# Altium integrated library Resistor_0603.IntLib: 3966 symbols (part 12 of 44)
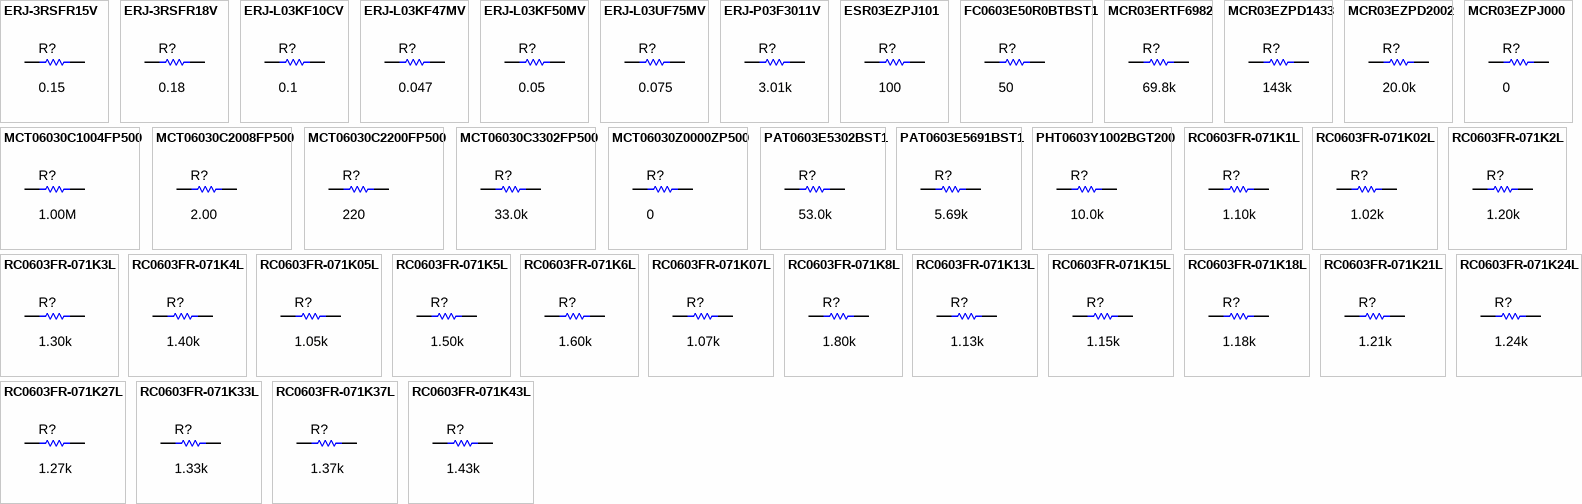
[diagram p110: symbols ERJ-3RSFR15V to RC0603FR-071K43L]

## RC0603FR-071K5L
designator R?  ValueDisplayed: 1.50k  (hidden comment: RC0603FR-071K5L)
RES, 1.50 k, 1%, 0.1 W, 0603; Manufacturer: Yageo America; CompType: Resistor; Value: 1.50k; Res_ohm: 1500; Value_Code: 1k50; Tolerance_%: 1; Power_W: 0.1; Value2: 0.1W; VDC_V: 150; TempCo: 200 ppm/C; SizeArea_mm2: 1.28; SizeX_mm: 1.6; SizeY_mm: 0.8; EIA_Code: E96; U/M: EA; AEC Category: Q200; Green_Lifecycle: Active; Green_REACh: Passed
signal-integrity model Resistor
simulation model Resistor
footprint 0603
footprint 0603M
footprint 0603L
footprint 0603_HV
footprint 0603S
pins: 1, 2

## RC0603FR-071K6L
designator R?  ValueDisplayed: 1.60k  (hidden comment: RC0603FR-071K6L)
RES, 1.60 k, 1%, 0.1 W, 0603; Manufacturer: Yageo America; CompType: Resistor; Value: 1.60k; Res_ohm: 1600; Value_Code: 1k60; Tolerance_%: 1; Power_W: 0.1; Value2: 0.1W; VDC_V: 150; TempCo: 200 ppm/C; SizeArea_mm2: 1.28; SizeX_mm: 1.6; SizeY_mm: 0.8; U/M: EA; AEC Category: Q200
signal-integrity model Resistor
simulation model Resistor
footprint 0603
footprint 0603M
footprint 0603L
footprint 0603_HV
footprint 0603S
pins: 1, 2

## RC0603FR-071K07L
designator R?  ValueDisplayed: 1.07k  (hidden comment: RC0603FR-071K07L)
RES, 1.07 k, 1%, 0.1 W, 0603; Manufacturer: Yageo America; CompType: Resistor; Value: 1.07k; Res_ohm: 1070; Value_Code: 1k07; Tolerance_%: 1; Power_W: 0.1; Value2: 0.1W; VDC_V: 150; TempCo: 200 ppm/C; SizeArea_mm2: 1.28; SizeX_mm: 1.6; SizeY_mm: 0.8; EIA_Code: E96; U/M: EA; AEC Category: Q200
signal-integrity model Resistor
simulation model Resistor
footprint 0603
footprint 0603M
footprint 0603L
footprint 0603_HV
footprint 0603S
pins: 1, 2

## RC0603FR-071K8L
designator R?  ValueDisplayed: 1.80k  (hidden comment: RC0603FR-071K8L)
RES, 1.80 k, 1%, 0.1 W, 0603; Manufacturer: Yageo America; CompType: Resistor; Value: 1.80k; Res_ohm: 1800; Value_Code: 1k80; Tolerance_%: 1; Power_W: 0.1; Value2: 0.1W; VDC_V: 150; TempCo: 200 ppm/C; SizeArea_mm2: 1.28; SizeX_mm: 1.6; SizeY_mm: 0.8; U/M: EA; AEC Category: Q200; Green_Lifecycle: Active; Green_REACh: Passed
signal-integrity model Resistor
simulation model Resistor
footprint 0603
footprint 0603M
footprint 0603L
footprint 0603_HV
footprint 0603S
pins: 1, 2

## RC0603FR-071K13L
designator R?  ValueDisplayed: 1.13k  (hidden comment: RC0603FR-071K13L)
RES, 1.13 k, 1%, 0.1 W, 0603; Manufacturer: Yageo America; CompType: Resistor; Value: 1.13k; Res_ohm: 1130; Value_Code: 1k13; Tolerance_%: 1; Power_W: 0.1; Value2: 0.1W; VDC_V: 150; TempCo: 200 ppm/C; SizeArea_mm2: 1.28; SizeX_mm: 1.6; SizeY_mm: 0.8; EIA_Code: E96; U/M: EA; AEC Category: Q200
signal-integrity model Resistor
simulation model Resistor
footprint 0603
footprint 0603M
footprint 0603L
footprint 0603_HV
footprint 0603S
pins: 1, 2

## RC0603FR-071K15L
designator R?  ValueDisplayed: 1.15k  (hidden comment: RC0603FR-071K15L)
RES, 1.15 k, 1%, 0.1 W, 0603; Manufacturer: Yageo America; CompType: Resistor; Value: 1.15k; Res_ohm: 1150; Value_Code: 1k15; Tolerance_%: 1; Power_W: 0.1; Value2: 0.1W; VDC_V: 150; TempCo: 200 ppm/C; SizeArea_mm2: 1.28; SizeX_mm: 1.6; SizeY_mm: 0.8; EIA_Code: E96; U/M: EA; AEC Category: Q200
signal-integrity model Resistor
simulation model Resistor
footprint 0603
footprint 0603M
footprint 0603L
footprint 0603_HV
footprint 0603S
pins: 1, 2

## RC0603FR-071K18L
designator R?  ValueDisplayed: 1.18k  (hidden comment: RC0603FR-071K18L)
RES, 1.18 k, 1%, 0.1 W, 0603; Manufacturer: Yageo America; CompType: Resistor; Value: 1.18k; Res_ohm: 1180; Value_Code: 1k18; Tolerance_%: 1; Power_W: 0.1; Value2: 0.1W; VDC_V: 150; TempCo: 200 ppm/C; SizeArea_mm2: 1.28; SizeX_mm: 1.6; SizeY_mm: 0.8; EIA_Code: E96; U/M: EA; AEC Category: Q200
signal-integrity model Resistor
simulation model Resistor
footprint 0603
footprint 0603M
footprint 0603L
footprint 0603_HV
footprint 0603S
pins: 1, 2

## RC0603FR-071K21L
designator R?  ValueDisplayed: 1.21k  (hidden comment: RC0603FR-071K21L)
RES, 1.21 k, 1%, 0.1 W, 0603; Manufacturer: Yageo America; CompType: Resistor; Value: 1.21k; Res_ohm: 1210; Value_Code: 1k21; Tolerance_%: 1; Power_W: 0.1; Value2: 0.1W; VDC_V: 150; TempCo: 200 ppm/C; SizeArea_mm2: 1.28; SizeX_mm: 1.6; SizeY_mm: 0.8; EIA_Code: E96; U/M: EA; AEC Category: Q200; Green_Lifecycle: Active; Green_REACh: Passed
signal-integrity model Resistor
simulation model Resistor
footprint 0603
footprint 0603M
footprint 0603L
footprint 0603_HV
footprint 0603S
pins: 1, 2

## RC0603FR-071K24L
designator R?  ValueDisplayed: 1.24k  (hidden comment: RC0603FR-071K24L)
RES, 1.24 k, 1%, 0.1 W, 0603; Manufacturer: Yageo America; CompType: Resistor; Value: 1.24k; Res_ohm: 1240; Value_Code: 1k24; Tolerance_%: 1; Power_W: 0.1; Value2: 0.1W; VDC_V: 150; TempCo: 200 ppm/C; SizeArea_mm2: 1.28; SizeX_mm: 1.6; SizeY_mm: 0.8; EIA_Code: E96; U/M: EA; AEC Category: Q200; Green_Lifecycle: Active; Green_REACh: Passed
signal-integrity model Resistor
simulation model Resistor
footprint 0603
footprint 0603M
footprint 0603L
footprint 0603_HV
footprint 0603S
pins: 1, 2

## RC0603FR-071K27L
designator R?  ValueDisplayed: 1.27k  (hidden comment: RC0603FR-071K27L)
RES, 1.27 k, 1%, 0.1 W, 0603; Manufacturer: Yageo America; CompType: Resistor; Value: 1.27k; Res_ohm: 1270; Value_Code: 1k27; Tolerance_%: 1; Power_W: 0.1; Value2: 0.1W; VDC_V: 150; TempCo: 200 ppm/C; SizeArea_mm2: 1.28; SizeX_mm: 1.6; SizeY_mm: 0.8; EIA_Code: E96; U/M: EA; AEC Category: Q200
signal-integrity model Resistor
simulation model Resistor
footprint 0603
footprint 0603M
footprint 0603L
footprint 0603_HV
footprint 0603S
pins: 1, 2

## RC0603FR-071K33L
designator R?  ValueDisplayed: 1.33k  (hidden comment: RC0603FR-071K33L)
RES, 1.33 k, 1%, 0.1 W, 0603; Manufacturer: Yageo America; CompType: Resistor; Value: 1.33k; Res_ohm: 1330; Value_Code: 1k33; Tolerance_%: 1; Power_W: 0.1; Value2: 0.1W; VDC_V: 150; TempCo: 200 ppm/C; SizeArea_mm2: 1.28; SizeX_mm: 1.6; SizeY_mm: 0.8; EIA_Code: E96; U/M: EA; AEC Category: Q200
signal-integrity model Resistor
simulation model Resistor
footprint 0603
footprint 0603M
footprint 0603L
footprint 0603_HV
footprint 0603S
pins: 1, 2

## RC0603FR-071K37L
designator R?  ValueDisplayed: 1.37k  (hidden comment: RC0603FR-071K37L)
RES, 1.37 k, 1%, 0.1 W, 0603; Manufacturer: Yageo America; CompType: Resistor; Value: 1.37k; Res_ohm: 1370; Value_Code: 1k37; Tolerance_%: 1; Power_W: 0.1; Value2: 0.1W; VDC_V: 150; TempCo: 200 ppm/C; SizeArea_mm2: 1.28; SizeX_mm: 1.6; SizeY_mm: 0.8; EIA_Code: E96; U/M: EA; AEC Category: Q200
signal-integrity model Resistor
simulation model Resistor
footprint 0603
footprint 0603M
footprint 0603L
footprint 0603_HV
footprint 0603S
pins: 1, 2

## RC0603FR-071K43L
designator R?  ValueDisplayed: 1.43k  (hidden comment: RC0603FR-071K43L)
RES, 1.43 k, 1%, 0.1 W, 0603; Manufacturer: Yageo America; CompType: Resistor; Value: 1.43k; Res_ohm: 1430; Value_Code: 1k43; Tolerance_%: 1; Power_W: 0.1; Value2: 0.1W; VDC_V: 150; TempCo: 200 ppm/C; SizeArea_mm2: 1.28; SizeX_mm: 1.6; SizeY_mm: 0.8; EIA_Code: E96; U/M: EA; AEC Category: Q200
signal-integrity model Resistor
simulation model Resistor
footprint 0603
footprint 0603M
footprint 0603L
footprint 0603_HV
footprint 0603S
pins: 1, 2

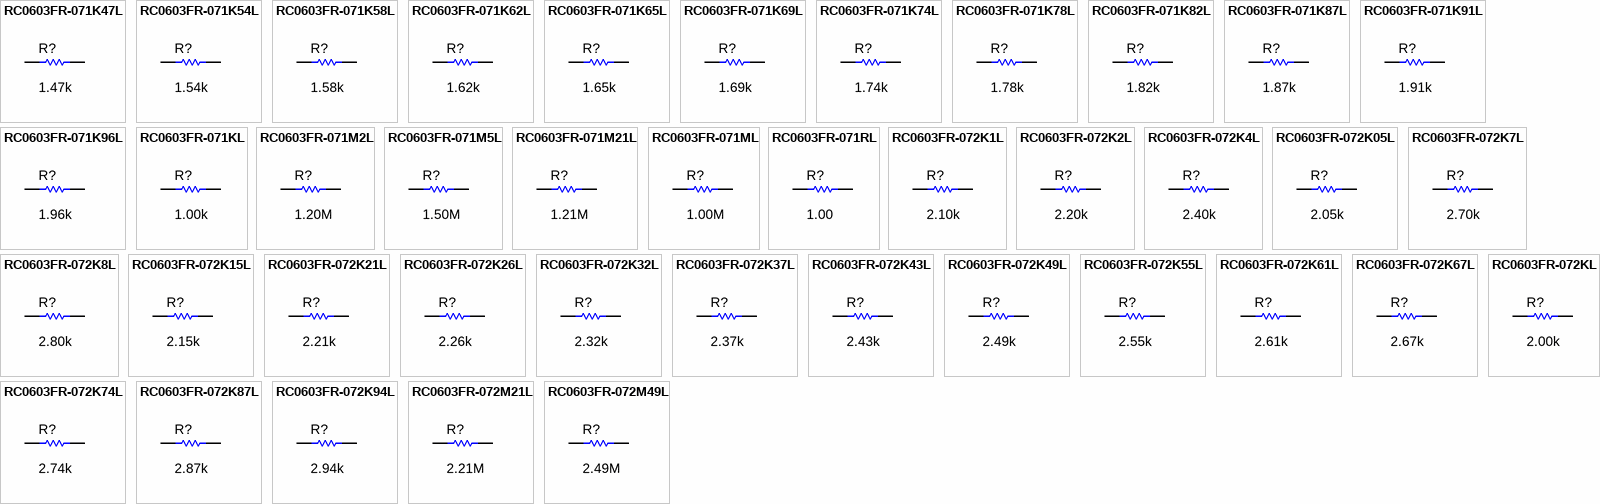
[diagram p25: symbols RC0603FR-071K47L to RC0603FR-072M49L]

## RC0603FR-071K47L
designator R?  ValueDisplayed: 1.47k  (hidden comment: RC0603FR-071K47L)
RES, 1.47 k, 1%, 0.1 W, 0603; Manufacturer: Yageo America; CompType: Resistor; Value: 1.47k; Res_ohm: 1470; Value_Code: 1k47; Tolerance_%: 1; Power_W: 0.1; Value2: 0.1W; VDC_V: 150; TempCo: 200 ppm/C; SizeArea_mm2: 1.28; SizeX_mm: 1.6; SizeY_mm: 0.8; EIA_Code: E96; U/M: EA; AEC Category: Q200
signal-integrity model Resistor
simulation model Resistor
footprint 0603
footprint 0603M
footprint 0603L
footprint 0603_HV
footprint 0603S
pins: 1, 2

## RC0603FR-071K54L
designator R?  ValueDisplayed: 1.54k  (hidden comment: RC0603FR-071K54L)
RES, 1.54 k, 1%, 0.1 W, 0603; Manufacturer: Yageo America; CompType: Resistor; Value: 1.54k; Res_ohm: 1540; Value_Code: 1k54; Tolerance_%: 1; Power_W: 0.1; Value2: 0.1W; VDC_V: 150; TempCo: 200 ppm/C; SizeArea_mm2: 1.28; SizeX_mm: 1.6; SizeY_mm: 0.8; EIA_Code: E96; U/M: EA; AEC Category: Q200; Green_Lifecycle: Not Set; Green_REACh: Incomplete
signal-integrity model Resistor
simulation model Resistor
footprint 0603
footprint 0603M
footprint 0603L
footprint 0603_HV
footprint 0603S
pins: 1, 2

## RC0603FR-071K58L
designator R?  ValueDisplayed: 1.58k  (hidden comment: RC0603FR-071K58L)
RES, 1.58 k, 1%, 0.1 W, 0603; Manufacturer: Yageo America; CompType: Resistor; Value: 1.58k; Res_ohm: 1580; Value_Code: 1k58; Tolerance_%: 1; Power_W: 0.1; Value2: 0.1W; VDC_V: 150; TempCo: 200 ppm/C; SizeArea_mm2: 1.28; SizeX_mm: 1.6; SizeY_mm: 0.8; EIA_Code: E96; U/M: EA; AEC Category: Q200; Green_Lifecycle: Active; Green_REACh: Passed
signal-integrity model Resistor
simulation model Resistor
footprint 0603
footprint 0603M
footprint 0603L
footprint 0603_HV
footprint 0603S
pins: 1, 2

## RC0603FR-071K62L
designator R?  ValueDisplayed: 1.62k  (hidden comment: RC0603FR-071K62L)
RES, 1.62 k, 1%, 0.1 W, 0603; Manufacturer: Yageo America; CompType: Resistor; Value: 1.62k; Res_ohm: 1620; Value_Code: 1k62; Tolerance_%: 1; Power_W: 0.1; Value2: 0.1W; VDC_V: 150; TempCo: 200 ppm/C; SizeArea_mm2: 1.28; SizeX_mm: 1.6; SizeY_mm: 0.8; EIA_Code: E96; U/M: EA; AEC Category: Q200; Green_Lifecycle: Active; Green_REACh: Passed
signal-integrity model Resistor
simulation model Resistor
footprint 0603
footprint 0603M
footprint 0603L
footprint 0603_HV
footprint 0603S
pins: 1, 2

## RC0603FR-071K65L
designator R?  ValueDisplayed: 1.65k  (hidden comment: RC0603FR-071K65L)
RES, 1.65 k, 1%, 0.1 W, 0603; Manufacturer: Yageo America; CompType: Resistor; Value: 1.65k; Res_ohm: 1650; Value_Code: 1k65; Tolerance_%: 1; Power_W: 0.1; Value2: 0.1W; VDC_V: 150; TempCo: 200 ppm/C; SizeArea_mm2: 1.28; SizeX_mm: 1.6; SizeY_mm: 0.8; EIA_Code: E96; U/M: EA; AEC Category: Q200
signal-integrity model Resistor
simulation model Resistor
footprint 0603
footprint 0603M
footprint 0603L
footprint 0603_HV
footprint 0603S
pins: 1, 2

## RC0603FR-071K69L
designator R?  ValueDisplayed: 1.69k  (hidden comment: RC0603FR-071K69L)
RES, 1.69 k, 1%, 0.1 W, 0603; Manufacturer: Yageo America; CompType: Resistor; Value: 1.69k; Res_ohm: 1690; Value_Code: 1k69; Tolerance_%: 1; Power_W: 0.1; Value2: 0.1W; VDC_V: 150; TempCo: 200 ppm/C; SizeArea_mm2: 1.28; SizeX_mm: 1.6; SizeY_mm: 0.8; EIA_Code: E96; U/M: EA; AEC Category: Q200
signal-integrity model Resistor
simulation model Resistor
footprint 0603
footprint 0603M
footprint 0603L
footprint 0603_HV
footprint 0603S
pins: 1, 2

## RC0603FR-071K74L
designator R?  ValueDisplayed: 1.74k  (hidden comment: RC0603FR-071K74L)
RES, 1.74 k, 1%, 0.1 W, 0603; Manufacturer: Yageo America; CompType: Resistor; Value: 1.74k; Res_ohm: 1740; Value_Code: 1k74; Tolerance_%: 1; Power_W: 0.1; Value2: 0.1W; VDC_V: 150; TempCo: 200 ppm/C; SizeArea_mm2: 1.28; SizeX_mm: 1.6; SizeY_mm: 0.8; EIA_Code: E96; U/M: EA; AEC Category: Q200
signal-integrity model Resistor
simulation model Resistor
footprint 0603
footprint 0603M
footprint 0603L
footprint 0603_HV
footprint 0603S
pins: 1, 2

## RC0603FR-071K78L
designator R?  ValueDisplayed: 1.78k  (hidden comment: RC0603FR-071K78L)
RES, 1.78 k, 1%, 0.1 W, 0603; Manufacturer: Yageo America; CompType: Resistor; Value: 1.78k; Res_ohm: 1780; Value_Code: 1k78; Tolerance_%: 1; Power_W: 0.1; Value2: 0.1W; VDC_V: 150; TempCo: 200 ppm/C; SizeArea_mm2: 1.28; SizeX_mm: 1.6; SizeY_mm: 0.8; EIA_Code: E96; U/M: EA; AEC Category: Q200
signal-integrity model Resistor
simulation model Resistor
footprint 0603
footprint 0603M
footprint 0603L
footprint 0603_HV
footprint 0603S
pins: 1, 2

## RC0603FR-071K82L
designator R?  ValueDisplayed: 1.82k  (hidden comment: RC0603FR-071K82L)
RES, 1.82 k, 1%, 0.1 W, 0603; Manufacturer: Yageo America; CompType: Resistor; Value: 1.82k; Res_ohm: 1820; Value_Code: 1k82; Tolerance_%: 1; Power_W: 0.1; Value2: 0.1W; VDC_V: 150; TempCo: 200 ppm/C; SizeArea_mm2: 1.28; SizeX_mm: 1.6; SizeY_mm: 0.8; EIA_Code: E96; U/M: EA; AEC Category: Q200; Green_Lifecycle: Active; Green_REACh: Passed
signal-integrity model Resistor
simulation model Resistor
footprint 0603
footprint 0603M
footprint 0603L
footprint 0603_HV
footprint 0603S
pins: 1, 2

## RC0603FR-071K87L
designator R?  ValueDisplayed: 1.87k  (hidden comment: RC0603FR-071K87L)
RES, 1.87 k, 1%, 0.1 W, 0603; Manufacturer: Yageo America; CompType: Resistor; Value: 1.87k; Res_ohm: 1870; Value_Code: 1k87; Tolerance_%: 1; Power_W: 0.1; Value2: 0.1W; VDC_V: 150; TempCo: 200 ppm/C; SizeArea_mm2: 1.28; SizeX_mm: 1.6; SizeY_mm: 0.8; EIA_Code: E96; U/M: EA; AEC Category: Q200; Green_Lifecycle: Active; Green_REACh: Passed
signal-integrity model Resistor
simulation model Resistor
footprint 0603
footprint 0603M
footprint 0603L
footprint 0603_HV
footprint 0603S
pins: 1, 2

## RC0603FR-071K91L
designator R?  ValueDisplayed: 1.91k  (hidden comment: RC0603FR-071K91L)
RES, 1.91 k, 1%, 0.1 W, 0603; Manufacturer: Yageo America; CompType: Resistor; Value: 1.91k; Res_ohm: 1910; Value_Code: 1k91; Tolerance_%: 1; Power_W: 0.1; Value2: 0.1W; VDC_V: 150; TempCo: 200 ppm/C; SizeArea_mm2: 1.28; SizeX_mm: 1.6; SizeY_mm: 0.8; EIA_Code: E96; U/M: EA; AEC Category: Q200; Green_Lifecycle: Active; Green_REACh: Passed
signal-integrity model Resistor
simulation model Resistor
footprint 0603
footprint 0603M
footprint 0603L
footprint 0603_HV
footprint 0603S
pins: 1, 2

## RC0603FR-071K96L
designator R?  ValueDisplayed: 1.96k  (hidden comment: RC0603FR-071K96L)
RES, 1.96 k, 1%, 0.1 W, 0603; Manufacturer: Yageo America; CompType: Resistor; Value: 1.96k; Res_ohm: 1960; Value_Code: 1k96; Tolerance_%: 1; Power_W: 0.1; Value2: 0.1W; VDC_V: 150; TempCo: 200 ppm/C; SizeArea_mm2: 1.28; SizeX_mm: 1.6; SizeY_mm: 0.8; EIA_Code: E96; U/M: EA; AEC Category: Q200
signal-integrity model Resistor
simulation model Resistor
footprint 0603
footprint 0603M
footprint 0603L
footprint 0603_HV
footprint 0603S
pins: 1, 2

## RC0603FR-071KL
designator R?  ValueDisplayed: 1.00k  (hidden comment: RC0603FR-071KL)
RES, 1.00 k, 1%, 0.1 W, 0603; Manufacturer: Yageo America; CompType: Resistor; Value: 1.00k; Res_ohm: 1000; Value_Code: 1k00; Tolerance_%: 1; Power_W: 0.1; Value2: 0.1W; VDC_V: 150; TempCo: 200 ppm/C; SizeArea_mm2: 1.28; SizeX_mm: 1.6; SizeY_mm: 0.8; EIA_Code: E96; U/M: EA; AEC Category: Q200; Green_Lifecycle: Active; Green_REACh: Passed
signal-integrity model Resistor
simulation model Resistor
footprint 0603
footprint 0603M
footprint 0603L
footprint 0603_HV
footprint 0603S
pins: 1, 2

## RC0603FR-071M2L
designator R?  ValueDisplayed: 1.20M  (hidden comment: RC0603FR-071M2L)
RES, 1.20 M, 1%, 0.1 W, 0603; Manufacturer: Yageo America; CompType: Resistor; Value: 1.20Meg; Res_ohm: 1200000; Value_Code: 1M20; Tolerance_%: 1; Power_W: 0.1; Value2: 0.1W; VDC_V: 150; TempCo: 200 ppm/C; SizeArea_mm2: 1.28; SizeX_mm: 1.6; SizeY_mm: 0.8; U/M: EA; AEC Category: Q200; Green_Lifecycle: Active; Green_REACh: Passed
signal-integrity model Resistor
simulation model Resistor
footprint 0603
footprint 0603M
footprint 0603L
footprint 0603_HV
footprint 0603S
pins: 1, 2

## RC0603FR-071M5L
designator R?  ValueDisplayed: 1.50M  (hidden comment: RC0603FR-071M5L)
RES, 1.50 M, 1%, 0.1 W, 0603; Manufacturer: Yageo America; CompType: Resistor; Value: 1.50Meg; Res_ohm: 1500000; Value_Code: 1M50; Tolerance_%: 1; Power_W: 0.1; Value2: 0.1W; VDC_V: 150; TempCo: 200 ppm/C; SizeArea_mm2: 1.28; SizeX_mm: 1.6; SizeY_mm: 0.8; EIA_Code: E96; U/M: EA; AEC Category: Q200
signal-integrity model Resistor
simulation model Resistor
footprint 0603
footprint 0603M
footprint 0603L
footprint 0603_HV
footprint 0603S
pins: 1, 2

## RC0603FR-071M21L
designator R?  ValueDisplayed: 1.21M  (hidden comment: RC0603FR-071M21L)
RES, 1.21 M, 1%, 0.1 W, 0603; Manufacturer: Yageo America; CompType: Resistor; Value: 1.21Meg; Res_ohm: 1210000; Value_Code: 1M21; Tolerance_%: 1; Power_W: 0.1; Value2: 0.1W; VDC_V: 150; TempCo: 200 ppm/C; SizeArea_mm2: 1.28; SizeX_mm: 1.6; SizeY_mm: 0.8; EIA_Code: E96; U/M: EA; AEC Category: Q200; Green_Lifecycle: Active; Green_REACh: Passed
signal-integrity model Resistor
simulation model Resistor
footprint 0603
footprint 0603M
footprint 0603L
footprint 0603_HV
footprint 0603S
pins: 1, 2

## RC0603FR-071ML
designator R?  ValueDisplayed: 1.00M  (hidden comment: RC0603FR-071ML)
RES, 1.00 M, 1%, 0.1 W, 0603; Manufacturer: Yageo America; CompType: Resistor; Value: 1.00Meg; Res_ohm: 1000000; Value_Code: 1M00; Tolerance_%: 1; Power_W: 0.1; Value2: 0.1W; VDC_V: 150; TempCo: 200 ppm/C; SizeArea_mm2: 1.28; SizeX_mm: 1.6; SizeY_mm: 0.8; EIA_Code: E96; U/M: EA; AEC Category: Q200; Green_Lifecycle: Active; Green_REACh: Passed
signal-integrity model Resistor
simulation model Resistor
footprint 0603
footprint 0603M
footprint 0603L
footprint 0603_HV
footprint 0603S
pins: 1, 2

## RC0603FR-071RL
designator R?  ValueDisplayed: 1.00  (hidden comment: RC0603FR-071RL)
RES, 1.00, 1%, 0.1 W, 0603; Manufacturer: Yageo America; CompType: Resistor; Value: 1.00; Res_ohm: 1; Value_Code: 1R00; Power_W: 0.1; Value2: 0.1W; VDC_V: 150; TempCo: 200 ppm/C; SizeArea_mm2: 1.28; SizeX_mm: 1.6; SizeY_mm: 0.8; EIA_Code: E96; U/M: EA; AEC Category: Q200; Green_Lifecycle: Active; Green_REACh: Passed
signal-integrity model Resistor
simulation model Resistor
footprint 0603
footprint 0603M
footprint 0603L
footprint 0603_HV
footprint 0603S
pins: 1, 2

## RC0603FR-072K1L
designator R?  ValueDisplayed: 2.10k  (hidden comment: RC0603FR-072K1L)
RES, 2.10 k, 1%, 0.1 W, 0603; Manufacturer: Yageo America; CompType: Resistor; Value: 2.10k; Res_ohm: 2100; Value_Code: 2k10; Tolerance_%: 1; Power_W: 0.1; Value2: 0.1W; VDC_V: 150; TempCo: 200 ppm/C; SizeArea_mm2: 1.28; SizeX_mm: 1.6; SizeY_mm: 0.8; EIA_Code: E96; U/M: EA; AEC Category: Q200; Green_Lifecycle: Active; Green_REACh: Passed
signal-integrity model Resistor
simulation model Resistor
footprint 0603
footprint 0603M
footprint 0603L
footprint 0603_HV
footprint 0603S
pins: 1, 2

## RC0603FR-072K2L
designator R?  ValueDisplayed: 2.20k  (hidden comment: RC0603FR-072K2L)
RES, 2.20 k, 1%, 0.1 W, 0603; Manufacturer: Yageo America; CompType: Resistor; Value: 2.20k; Res_ohm: 2200; Value_Code: 2k20; Tolerance_%: 1; Power_W: 0.1; Value2: 0.1W; VDC_V: 150; TempCo: 200 ppm/C; SizeArea_mm2: 1.28; SizeX_mm: 1.6; SizeY_mm: 0.8; U/M: EA; AEC Category: Q200; Green_Lifecycle: Active; Green_REACh: Passed
signal-integrity model Resistor
simulation model Resistor
footprint 0603
footprint 0603M
footprint 0603L
footprint 0603_HV
footprint 0603S
pins: 1, 2

## RC0603FR-072K4L
designator R?  ValueDisplayed: 2.40k  (hidden comment: RC0603FR-072K4L)
RES, 2.40 k, 1%, 0.1 W, 0603; Manufacturer: Yageo America; CompType: Resistor; Value: 2.40k; Res_ohm: 2400; Value_Code: 2k40; Tolerance_%: 1; Power_W: 0.1; Value2: 0.1W; VDC_V: 150; TempCo: 200 ppm/C; SizeArea_mm2: 1.28; SizeX_mm: 1.6; SizeY_mm: 0.8; U/M: EA; AEC Category: Q200
signal-integrity model Resistor
simulation model Resistor
footprint 0603
footprint 0603M
footprint 0603L
footprint 0603_HV
footprint 0603S
pins: 1, 2

## RC0603FR-072K05L
designator R?  ValueDisplayed: 2.05k  (hidden comment: RC0603FR-072K05L)
RES, 2.05 k, 1%, 0.1 W, 0603; Manufacturer: Yageo America; CompType: Resistor; Value: 2.05k; Res_ohm: 2050; Value_Code: 2k05; Tolerance_%: 1; Power_W: 0.1; Value2: 0.1W; VDC_V: 150; TempCo: 200 ppm/C; SizeArea_mm2: 1.28; SizeX_mm: 1.6; SizeY_mm: 0.8; EIA_Code: E96; U/M: EA; AEC Category: Q200; Green_Lifecycle: Active; Green_REACh: Passed
signal-integrity model Resistor
simulation model Resistor
footprint 0603
footprint 0603M
footprint 0603L
footprint 0603_HV
footprint 0603S
pins: 1, 2

## RC0603FR-072K7L
designator R?  ValueDisplayed: 2.70k  (hidden comment: RC0603FR-072K7L)
RES, 2.70 k, 1%, 0.1 W, 0603; Manufacturer: Yageo America; CompType: Resistor; Value: 2.70k; Res_ohm: 2700; Value_Code: 2k70; Tolerance_%: 1; Power_W: 0.1; Value2: 0.1W; VDC_V: 150; TempCo: 200 ppm/C; SizeArea_mm2: 1.28; SizeX_mm: 1.6; SizeY_mm: 0.8; U/M: EA; AEC Category: Q200
signal-integrity model Resistor
simulation model Resistor
footprint 0603
footprint 0603M
footprint 0603L
footprint 0603_HV
footprint 0603S
pins: 1, 2

## RC0603FR-072K8L
designator R?  ValueDisplayed: 2.80k  (hidden comment: RC0603FR-072K8L)
RES, 2.80 k, 1%, 0.1 W, 0603; Manufacturer: Yageo America; CompType: Resistor; Value: 2.80k; Res_ohm: 2800; Value_Code: 2k80; Tolerance_%: 1; Power_W: 0.1; Value2: 0.1W; VDC_V: 150; TempCo: 200 ppm/C; SizeArea_mm2: 1.28; SizeX_mm: 1.6; SizeY_mm: 0.8; EIA_Code: E96; U/M: EA; AEC Category: Q200
signal-integrity model Resistor
simulation model Resistor
footprint 0603
footprint 0603M
footprint 0603L
footprint 0603_HV
footprint 0603S
pins: 1, 2

## RC0603FR-072K15L
designator R?  ValueDisplayed: 2.15k  (hidden comment: RC0603FR-072K15L)
RES, 2.15 k, 1%, 0.1 W, 0603; Manufacturer: Yageo America; CompType: Resistor; Value: 2.15k; Res_ohm: 2150; Value_Code: 2k15; Tolerance_%: 1; Power_W: 0.1; Value2: 0.1W; VDC_V: 150; TempCo: 200 ppm/C; SizeArea_mm2: 1.28; SizeX_mm: 1.6; SizeY_mm: 0.8; EIA_Code: E96; U/M: EA; AEC Category: Q200
signal-integrity model Resistor
simulation model Resistor
footprint 0603
footprint 0603M
footprint 0603L
footprint 0603_HV
footprint 0603S
pins: 1, 2

## RC0603FR-072K21L
designator R?  ValueDisplayed: 2.21k  (hidden comment: RC0603FR-072K21L)
RES, 2.21 k, 1%, 0.1 W, 0603; Manufacturer: Yageo America; CompType: Resistor; Value: 2.21k; Res_ohm: 2210; Value_Code: 2k21; Tolerance_%: 1; Power_W: 0.1; Value2: 0.1W; VDC_V: 150; TempCo: 200 ppm/C; SizeArea_mm2: 1.28; SizeX_mm: 1.6; SizeY_mm: 0.8; EIA_Code: E96; U/M: EA; AEC Category: Q200; Green_Lifecycle: Active; Green_REACh: Passed
signal-integrity model Resistor
simulation model Resistor
footprint 0603
footprint 0603M
footprint 0603L
footprint 0603_HV
footprint 0603S
pins: 1, 2

## RC0603FR-072K26L
designator R?  ValueDisplayed: 2.26k  (hidden comment: RC0603FR-072K26L)
RES, 2.26 k, 1%, 0.1 W, 0603; Manufacturer: Yageo America; CompType: Resistor; Value: 2.26k; Res_ohm: 2260; Value_Code: 2k26; Tolerance_%: 1; Power_W: 0.1; Value2: 0.1W; VDC_V: 150; TempCo: 200 ppm/C; SizeArea_mm2: 1.28; SizeX_mm: 1.6; SizeY_mm: 0.8; EIA_Code: E96; U/M: EA; AEC Category: Q200; Green_Lifecycle: Active; Green_REACh: Passed
signal-integrity model Resistor
simulation model Resistor
footprint 0603
footprint 0603M
footprint 0603L
footprint 0603_HV
footprint 0603S
pins: 1, 2

## RC0603FR-072K32L
designator R?  ValueDisplayed: 2.32k  (hidden comment: RC0603FR-072K32L)
RES, 2.32 k, 1%, 0.1 W, 0603; Manufacturer: Yageo America; CompType: Resistor; Value: 2.32k; Res_ohm: 2320; Value_Code: 2k32; Tolerance_%: 1; Power_W: 0.1; Value2: 0.1W; VDC_V: 150; TempCo: 200 ppm/C; SizeArea_mm2: 1.28; SizeX_mm: 1.6; SizeY_mm: 0.8; EIA_Code: E96; U/M: EA; AEC Category: Q200; Green_Lifecycle: Active; Green_REACh: Passed
signal-integrity model Resistor
simulation model Resistor
footprint 0603
footprint 0603M
footprint 0603L
footprint 0603_HV
footprint 0603S
pins: 1, 2

## RC0603FR-072K37L
designator R?  ValueDisplayed: 2.37k  (hidden comment: RC0603FR-072K37L)
RES, 2.37 k, 1%, 0.1 W, 0603; Manufacturer: Yageo America; CompType: Resistor; Value: 2.37k; Res_ohm: 2370; Value_Code: 2k37; Tolerance_%: 1; Power_W: 0.1; Value2: 0.1W; VDC_V: 150; TempCo: 200 ppm/C; SizeArea_mm2: 1.28; SizeX_mm: 1.6; SizeY_mm: 0.8; EIA_Code: E96; U/M: EA; AEC Category: Q200; Green_Lifecycle: Active; Green_REACh: Passed
signal-integrity model Resistor
simulation model Resistor
footprint 0603
footprint 0603M
footprint 0603L
footprint 0603_HV
footprint 0603S
pins: 1, 2

## RC0603FR-072K43L
designator R?  ValueDisplayed: 2.43k  (hidden comment: RC0603FR-072K43L)
RES, 2.43 k, 1%, 0.1 W, 0603; Manufacturer: Yageo America; CompType: Resistor; Value: 2.43k; Res_ohm: 2430; Value_Code: 2k43; Tolerance_%: 1; Power_W: 0.1; Value2: 0.1W; VDC_V: 150; TempCo: 200 ppm/C; SizeArea_mm2: 1.28; SizeX_mm: 1.6; SizeY_mm: 0.8; EIA_Code: E96; U/M: EA; AEC Category: Q200
signal-integrity model Resistor
simulation model Resistor
footprint 0603
footprint 0603M
footprint 0603L
footprint 0603_HV
footprint 0603S
pins: 1, 2

## RC0603FR-072K49L
designator R?  ValueDisplayed: 2.49k  (hidden comment: RC0603FR-072K49L)
RES, 2.49 k, 1%, 0.1 W, 0603; Manufacturer: Yageo America; CompType: Resistor; Value: 2.49k; Res_ohm: 2490; Value_Code: 2k49; Tolerance_%: 1; Power_W: 0.1; Value2: 0.1W; VDC_V: 150; TempCo: 200 ppm/C; SizeArea_mm2: 1.28; SizeX_mm: 1.6; SizeY_mm: 0.8; EIA_Code: E96; U/M: EA; AEC Category: Q200; Green_Lifecycle: Active; Green_REACh: Passed
signal-integrity model Resistor
simulation model Resistor
footprint 0603
footprint 0603M
footprint 0603L
footprint 0603_HV
footprint 0603S
pins: 1, 2

## RC0603FR-072K55L
designator R?  ValueDisplayed: 2.55k  (hidden comment: RC0603FR-072K55L)
RES, 2.55 k, 1%, 0.1 W, 0603; Manufacturer: Yageo America; CompType: Resistor; Value: 2.55k; Res_ohm: 2550; Value_Code: 2k55; Tolerance_%: 1; Power_W: 0.1; Value2: 0.1W; VDC_V: 150; TempCo: 200 ppm/C; SizeArea_mm2: 1.28; SizeX_mm: 1.6; SizeY_mm: 0.8; EIA_Code: E96; U/M: EA; AEC Category: Q200
signal-integrity model Resistor
simulation model Resistor
footprint 0603
footprint 0603M
footprint 0603L
footprint 0603_HV
footprint 0603S
pins: 1, 2

## RC0603FR-072K61L
designator R?  ValueDisplayed: 2.61k  (hidden comment: RC0603FR-072K61L)
RES, 2.61 k, 1%, 0.1 W, 0603; Manufacturer: Yageo America; CompType: Resistor; Value: 2.61k; Res_ohm: 2610; Value_Code: 2k61; Tolerance_%: 1; Power_W: 0.1; Value2: 0.1W; VDC_V: 150; TempCo: 200 ppm/C; SizeArea_mm2: 1.28; SizeX_mm: 1.6; SizeY_mm: 0.8; EIA_Code: E96; U/M: EA; AEC Category: Q200
signal-integrity model Resistor
simulation model Resistor
footprint 0603
footprint 0603M
footprint 0603L
footprint 0603_HV
footprint 0603S
pins: 1, 2

## RC0603FR-072K67L
designator R?  ValueDisplayed: 2.67k  (hidden comment: RC0603FR-072K67L)
RES, 2.67 k, 1%, 0.1 W, 0603; Manufacturer: Yageo America; CompType: Resistor; Value: 2.67k; Res_ohm: 2670; Value_Code: 2k67; Tolerance_%: 1; Power_W: 0.1; Value2: 0.1W; VDC_V: 150; TempCo: 200 ppm/C; SizeArea_mm2: 1.28; SizeX_mm: 1.6; SizeY_mm: 0.8; EIA_Code: E96; U/M: EA; AEC Category: Q200; Green_Lifecycle: Active; Green_REACh: Passed
signal-integrity model Resistor
simulation model Resistor
footprint 0603
footprint 0603M
footprint 0603L
footprint 0603_HV
footprint 0603S
pins: 1, 2

## RC0603FR-072K74L
designator R?  ValueDisplayed: 2.74k  (hidden comment: RC0603FR-072K74L)
RES, 2.74 k, 1%, 0.1 W, 0603; Manufacturer: Yageo America; CompType: Resistor; Value: 2.74k; Res_ohm: 2740; Value_Code: 2k74; Tolerance_%: 1; Power_W: 0.1; Value2: 0.1W; VDC_V: 150; TempCo: 200 ppm/C; SizeArea_mm2: 1.28; SizeX_mm: 1.6; SizeY_mm: 0.8; EIA_Code: E96; U/M: EA; AEC Category: Q200; Green_Lifecycle: Active; Green_REACh: Passed
signal-integrity model Resistor
simulation model Resistor
footprint 0603
footprint 0603M
footprint 0603L
footprint 0603_HV
footprint 0603S
pins: 1, 2

## RC0603FR-072K87L
designator R?  ValueDisplayed: 2.87k  (hidden comment: RC0603FR-072K87L)
RES, 2.87 k, 1%, 0.1 W, 0603; Manufacturer: Yageo America; CompType: Resistor; Value: 2.87k; Res_ohm: 2870; Value_Code: 2k87; Tolerance_%: 1; Power_W: 0.1; Value2: 0.1W; VDC_V: 150; TempCo: 200 ppm/C; SizeArea_mm2: 1.28; SizeX_mm: 1.6; SizeY_mm: 0.8; EIA_Code: E96; U/M: EA; AEC Category: Q200
signal-integrity model Resistor
simulation model Resistor
footprint 0603
footprint 0603M
footprint 0603L
footprint 0603_HV
footprint 0603S
pins: 1, 2

## RC0603FR-072K94L
designator R?  ValueDisplayed: 2.94k  (hidden comment: RC0603FR-072K94L)
RES, 2.94 k, 1%, 0.1 W, 0603; Manufacturer: Yageo America; CompType: Resistor; Value: 2.94k; Res_ohm: 2940; Value_Code: 2k94; Tolerance_%: 1; Power_W: 0.1; Value2: 0.1W; VDC_V: 150; TempCo: 200 ppm/C; SizeArea_mm2: 1.28; SizeX_mm: 1.6; SizeY_mm: 0.8; EIA_Code: E96; U/M: EA; AEC Category: Q200
signal-integrity model Resistor
simulation model Resistor
footprint 0603
footprint 0603M
footprint 0603L
footprint 0603_HV
footprint 0603S
pins: 1, 2

## RC0603FR-072KL
designator R?  ValueDisplayed: 2.00k  (hidden comment: RC0603FR-072KL)
RES, 2.00 k, 1%, 0.1 W, 0603; Manufacturer: Yageo America; CompType: Resistor; Value: 2.00k; Res_ohm: 2000; Value_Code: 2k00; Tolerance_%: 1; Power_W: 0.1; Value2: 0.1W; VDC_V: 150; TempCo: 200 ppm/C; SizeArea_mm2: 1.28; SizeX_mm: 1.6; SizeY_mm: 0.8; EIA_Code: E96; U/M: EA; AEC Category: Q200; Green_Lifecycle: Active; Green_REACh: Passed
signal-integrity model Resistor
simulation model Resistor
footprint 0603
footprint 0603M
footprint 0603L
footprint 0603_HV
footprint 0603S
pins: 1, 2

## RC0603FR-072M21L
designator R?  ValueDisplayed: 2.21M  (hidden comment: RC0603FR-072M21L)
RES, 2.21 M, 1%, 0.1 W, 0603; Manufacturer: Yageo America; CompType: Resistor; Value: 2.21Meg; Res_ohm: 2210000; Value_Code: 2M21; Tolerance_%: 1; Power_W: 0.1; Value2: 0.1W; VDC_V: 150; TempCo: 200 ppm/C; SizeArea_mm2: 1.28; SizeX_mm: 1.6; SizeY_mm: 0.8; EIA_Code: E96; U/M: EA; AEC Category: Q200; Green_Lifecycle: Active; Green_REACh: Passed
signal-integrity model Resistor
simulation model Resistor
footprint 0603
footprint 0603M
footprint 0603L
footprint 0603_HV
footprint 0603S
pins: 1, 2

## RC0603FR-072M49L
designator R?  ValueDisplayed: 2.49M  (hidden comment: RC0603FR-072M49L)
RES, 2.49 M, 1%, 0.1 W, 0603; Manufacturer: Yageo America; CompType: Resistor; Value: 2.49Meg; Res_ohm: 2490000; Value_Code: 2M49; Tolerance_%: 1; Power_W: 0.1; Value2: 0.1W; VDC_V: 150; TempCo: 200 ppm/C; SizeArea_mm2: 1.28; SizeX_mm: 1.6; SizeY_mm: 0.8; EIA_Code: E96; U/M: EA; AEC Category: Q200
signal-integrity model Resistor
simulation model Resistor
footprint 0603
footprint 0603M
footprint 0603L
footprint 0603_HV
footprint 0603S
pins: 1, 2

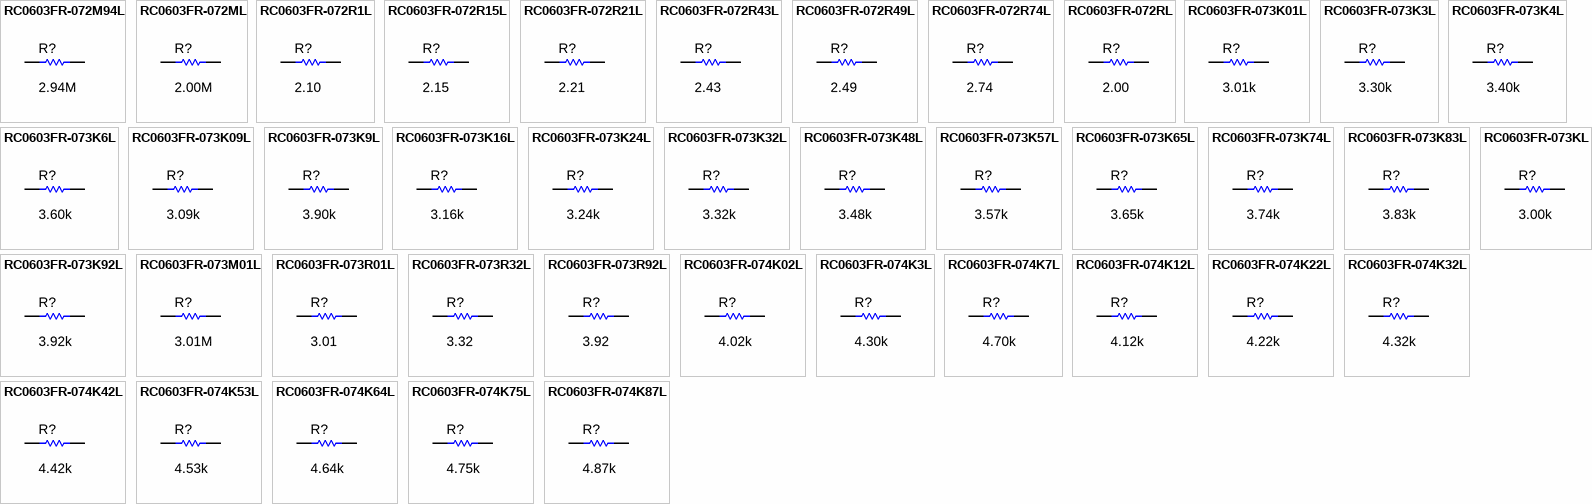
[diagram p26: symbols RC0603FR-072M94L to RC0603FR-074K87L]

## RC0603FR-072M94L
designator R?  ValueDisplayed: 2.94M  (hidden comment: RC0603FR-072M94L)
RES, 2.94 M, 1%, 0.1 W, 0603; Manufacturer: Yageo America; CompType: Resistor; Value: 2.94Meg; Res_ohm: 2940000; Value_Code: 2M94; Tolerance_%: 1; Power_W: 0.1; Value2: 0.1W; VDC_V: 150; TempCo: 200 ppm/C; SizeArea_mm2: 1.28; SizeX_mm: 1.6; SizeY_mm: 0.8; EIA_Code: E96; U/M: EA; AEC Category: Q200
signal-integrity model Resistor
simulation model Resistor
footprint 0603
footprint 0603M
footprint 0603L
footprint 0603_HV
footprint 0603S
pins: 1, 2

## RC0603FR-072ML
designator R?  ValueDisplayed: 2.00M  (hidden comment: RC0603FR-072ML)
RES, 2.00 M, 1%, 0.1 W, 0603; Manufacturer: Yageo America; CompType: Resistor; Value: 2.00Meg; Res_ohm: 2000000; Value_Code: 2M00; Tolerance_%: 1; Power_W: 0.1; Value2: 0.1W; VDC_V: 150; TempCo: 200 ppm/C; SizeArea_mm2: 1.28; SizeX_mm: 1.6; SizeY_mm: 0.8; EIA_Code: E96; U/M: EA; AEC Category: Q200; Green_Lifecycle: Active; Green_REACh: Passed
signal-integrity model Resistor
simulation model Resistor
footprint 0603
footprint 0603M
footprint 0603L
footprint 0603_HV
footprint 0603S
pins: 1, 2

## RC0603FR-072R1L
designator R?  ValueDisplayed: 2.10  (hidden comment: RC0603FR-072R1L)
RES, 2.10, 1%, 0.1 W, 0603; Manufacturer: Yageo America; CompType: Resistor; Value: 2.10; Res_ohm: 2.1; Value_Code: 2R10; Tolerance_%: 1; Power_W: 0.1; Value2: 0.1W; VDC_V: 150; TempCo: 200 ppm/C; SizeArea_mm2: 1.28; SizeX_mm: 1.6; SizeY_mm: 0.8; EIA_Code: E96; U/M: EA; AEC Category: Q200
signal-integrity model Resistor
simulation model Resistor
footprint 0603
footprint 0603M
footprint 0603L
footprint 0603_HV
footprint 0603S
pins: 1, 2

## RC0603FR-072R15L
designator R?  ValueDisplayed: 2.15  (hidden comment: RC0603FR-072R15L)
RES, 2.15, 1%, 0.1 W, 0603; Manufacturer: Yageo America; CompType: Resistor; Value: 2.15; Value_Code: 2R15; Tolerance_%: 1; Power_W: 0.1; Value2: 0.1W; VDC_V: 150; TempCo: 200 ppm/C; SizeArea_mm2: 1.28; SizeX_mm: 1.6; SizeY_mm: 0.8; EIA_Code: E96; U/M: EA; AEC Category: Q200
signal-integrity model Resistor
simulation model Resistor
footprint 0603
footprint 0603M
footprint 0603L
footprint 0603_HV
footprint 0603S
pins: 1, 2

## RC0603FR-072R21L
designator R?  ValueDisplayed: 2.21  (hidden comment: RC0603FR-072R21L)
RES, 2.21, 1%, 0.1 W, 0603; Manufacturer: Yageo America; CompType: Resistor; Value: 2.21; Value_Code: 2R21; Tolerance_%: 1; Power_W: 0.1; Value2: 0.1W; VDC_V: 150; TempCo: 200 ppm/C; SizeArea_mm2: 1.28; SizeX_mm: 1.6; SizeY_mm: 0.8; EIA_Code: E96; U/M: EA; AEC Category: Q200
signal-integrity model Resistor
simulation model Resistor
footprint 0603
footprint 0603M
footprint 0603L
footprint 0603_HV
footprint 0603S
pins: 1, 2

## RC0603FR-072R43L
designator R?  ValueDisplayed: 2.43  (hidden comment: RC0603FR-072R43L)
RES, 2.43, 1%, 0.1 W, 0603; Manufacturer: Yageo America; CompType: Resistor; Value: 2.43; Value_Code: 2R43; Tolerance_%: 1; Power_W: 0.1; Value2: 0.1W; VDC_V: 150; TempCo: 200 ppm/C; SizeArea_mm2: 1.28; SizeX_mm: 1.6; SizeY_mm: 0.8; EIA_Code: E96; U/M: EA; AEC Category: Q200
signal-integrity model Resistor
simulation model Resistor
footprint 0603
footprint 0603M
footprint 0603L
footprint 0603_HV
footprint 0603S
pins: 1, 2

## RC0603FR-072R49L
designator R?  ValueDisplayed: 2.49  (hidden comment: RC0603FR-072R49L)
RES, 2.49, 1%, 0.1 W, 0603; Manufacturer: Yageo America; CompType: Resistor; Value: 2.49; Value_Code: 2R49; Tolerance_%: 1; Power_W: 0.1; Value2: 0.1W; VDC_V: 150; TempCo: 200 ppm/C; SizeArea_mm2: 1.28; SizeX_mm: 1.6; SizeY_mm: 0.8; EIA_Code: E96; U/M: EA; AEC Category: Q200
signal-integrity model Resistor
simulation model Resistor
footprint 0603
footprint 0603M
footprint 0603L
footprint 0603_HV
footprint 0603S
pins: 1, 2

## RC0603FR-072R74L
designator R?  ValueDisplayed: 2.74  (hidden comment: RC0603FR-072R74L)
RES, 2.74, 1%, 0.1 W, 0603; Manufacturer: Yageo America; CompType: Resistor; Value: 2.74; Value_Code: 2R74; Tolerance_%: 1; Power_W: 0.1; Value2: 0.1W; VDC_V: 150; TempCo: 200 ppm/C; SizeArea_mm2: 1.28; SizeX_mm: 1.6; SizeY_mm: 0.8; EIA_Code: E96; U/M: EA; AEC Category: Q200
signal-integrity model Resistor
simulation model Resistor
footprint 0603
footprint 0603M
footprint 0603L
footprint 0603_HV
footprint 0603S
pins: 1, 2

## RC0603FR-072RL
designator R?  ValueDisplayed: 2.00  (hidden comment: RC0603FR-072RL)
RES, 2.00, 1%, 0.1 W, 0603; Manufacturer: Yageo America; CompType: Resistor; Value: 2.00; Res_ohm: 2; Value_Code: 2R00; Tolerance_%: 1; Power_W: 0.1; Value2: 0.1W; VDC_V: 150; TempCo: 200 ppm/C; SizeArea_mm2: 1.28; SizeX_mm: 1.6; SizeY_mm: 0.8; EIA_Code: E96; U/M: EA; AEC Category: Q200
signal-integrity model Resistor
simulation model Resistor
footprint 0603
footprint 0603M
footprint 0603L
footprint 0603_HV
footprint 0603S
pins: 1, 2

## RC0603FR-073K01L
designator R?  ValueDisplayed: 3.01k  (hidden comment: RC0603FR-073K01L)
RES, 3.01 k, 1%, 0.1 W, 0603; Manufacturer: Yageo America; CompType: Resistor; Value: 3.01k; Res_ohm: 3010; Value_Code: 3k01; Tolerance_%: 1; Power_W: 0.1; Value2: 0.1W; VDC_V: 150; TempCo: 200 ppm/C; SizeArea_mm2: 1.28; SizeX_mm: 1.6; SizeY_mm: 0.8; EIA_Code: E96; U/M: EA; AEC Category: Q200; Green_Lifecycle: Active; Green_REACh: Passed
signal-integrity model Resistor
simulation model Resistor
footprint 0603
footprint 0603M
footprint 0603L
footprint 0603_HV
footprint 0603S
pins: 1, 2

## RC0603FR-073K3L
designator R?  ValueDisplayed: 3.30k  (hidden comment: RC0603FR-073K3L)
RES, 3.30 k, 1%, 0.1 W, 0603; Manufacturer: Yageo America; CompType: Resistor; Value: 3.30k; Res_ohm: 3300; Value_Code: 3k30; Tolerance_%: 1; Power_W: 0.1; Value2: 0.1W; VDC_V: 150; TempCo: 200 ppm/C; SizeArea_mm2: 1.28; SizeX_mm: 1.6; SizeY_mm: 0.8; U/M: EA; AEC Category: Q200; Green_Lifecycle: Active; Green_REACh: Passed
signal-integrity model Resistor
simulation model Resistor
footprint 0603
footprint 0603M
footprint 0603L
footprint 0603_HV
footprint 0603S
pins: 1, 2

## RC0603FR-073K4L
designator R?  ValueDisplayed: 3.40k  (hidden comment: RC0603FR-073K4L)
RES, 3.40 k, 1%, 0.1 W, 0603; Manufacturer: Yageo America; CompType: Resistor; Value: 3.40k; Res_ohm: 3400; Value_Code: 3k40; Tolerance_%: 1; Power_W: 0.1; Value2: 0.1W; VDC_V: 150; TempCo: 200 ppm/C; SizeArea_mm2: 1.28; SizeX_mm: 1.6; SizeY_mm: 0.8; EIA_Code: E96; U/M: EA; AEC Category: Q200; Green_Lifecycle: Active; Green_REACh: Passed
signal-integrity model Resistor
simulation model Resistor
footprint 0603
footprint 0603M
footprint 0603L
footprint 0603_HV
footprint 0603S
pins: 1, 2

## RC0603FR-073K6L
designator R?  ValueDisplayed: 3.60k  (hidden comment: RC0603FR-073K6L)
RES, 3.60 k, 1%, 0.1 W, 0603; Manufacturer: Yageo America; CompType: Resistor; Value: 3.60k; Res_ohm: 3600; Value_Code: 3k60; Tolerance_%: 1; Power_W: 0.1; Value2: 0.1W; VDC_V: 150; TempCo: 200 ppm/C; SizeArea_mm2: 1.28; SizeX_mm: 1.6; SizeY_mm: 0.8; U/M: EA; AEC Category: Q200; Green_Lifecycle: Active; Green_REACh: Passed
signal-integrity model Resistor
simulation model Resistor
footprint 0603
footprint 0603M
footprint 0603L
footprint 0603_HV
footprint 0603S
pins: 1, 2

## RC0603FR-073K09L
designator R?  ValueDisplayed: 3.09k  (hidden comment: RC0603FR-073K09L)
RES, 3.09 k, 1%, 0.1 W, 0603; Manufacturer: Yageo America; CompType: Resistor; Value: 3.09k; Res_ohm: 3090; Value_Code: 3k09; Tolerance_%: 1; Power_W: 0.1; Value2: 0.1W; VDC_V: 150; TempCo: 200 ppm/C; SizeArea_mm2: 1.28; SizeX_mm: 1.6; SizeY_mm: 0.8; EIA_Code: E96; U/M: EA; AEC Category: Q200
signal-integrity model Resistor
simulation model Resistor
footprint 0603
footprint 0603M
footprint 0603L
footprint 0603_HV
footprint 0603S
pins: 1, 2

## RC0603FR-073K9L
designator R?  ValueDisplayed: 3.90k  (hidden comment: RC0603FR-073K9L)
RES, 3.90 k, 1%, 0.1 W, 0603; Manufacturer: Yageo America; CompType: Resistor; Value: 3.90k; Res_ohm: 3900; Value_Code: 3k90; Tolerance_%: 1; Power_W: 0.1; Value2: 0.1W; VDC_V: 150; TempCo: 200 ppm/C; SizeArea_mm2: 1.28; SizeX_mm: 1.6; SizeY_mm: 0.8; U/M: EA; AEC Category: Q200; Green_Lifecycle: Active; Green_REACh: Passed
signal-integrity model Resistor
simulation model Resistor
footprint 0603
footprint 0603M
footprint 0603L
footprint 0603_HV
footprint 0603S
pins: 1, 2

## RC0603FR-073K16L
designator R?  ValueDisplayed: 3.16k  (hidden comment: RC0603FR-073K16L)
RES, 3.16 k, 1%, 0.1 W, 0603; Manufacturer: Yageo America; CompType: Resistor; Value: 3.16k; Res_ohm: 3160; Value_Code: 3k16; Tolerance_%: 1; Power_W: 0.1; Value2: 0.1W; VDC_V: 150; TempCo: 200 ppm/C; SizeArea_mm2: 1.28; SizeX_mm: 1.6; SizeY_mm: 0.8; EIA_Code: E96; U/M: EA; AEC Category: Q200; Green_Lifecycle: Active; Green_REACh: Passed
signal-integrity model Resistor
simulation model Resistor
footprint 0603
footprint 0603M
footprint 0603L
footprint 0603_HV
footprint 0603S
pins: 1, 2

## RC0603FR-073K24L
designator R?  ValueDisplayed: 3.24k  (hidden comment: RC0603FR-073K24L)
RES, 3.24 k, 1%, 0.1 W, 0603; Manufacturer: Yageo America; CompType: Resistor; Value: 3.24k; Res_ohm: 3240; Value_Code: 3k24; Tolerance_%: 1; Power_W: 0.1; Value2: 0.1W; VDC_V: 150; TempCo: 200 ppm/C; SizeArea_mm2: 1.28; SizeX_mm: 1.6; SizeY_mm: 0.8; EIA_Code: E96; U/M: EA; AEC Category: Q200; Green_Lifecycle: Active; Green_REACh: Passed
signal-integrity model Resistor
simulation model Resistor
footprint 0603
footprint 0603M
footprint 0603L
footprint 0603_HV
footprint 0603S
pins: 1, 2

## RC0603FR-073K32L
designator R?  ValueDisplayed: 3.32k  (hidden comment: RC0603FR-073K32L)
RES, 3.32 k, 1%, 0.1 W, 0603; Manufacturer: Yageo America; CompType: Resistor; Value: 3.32k; Res_ohm: 3320; Value_Code: 3k32; Tolerance_%: 1; Power_W: 0.1; Value2: 0.1W; VDC_V: 150; TempCo: 200 ppm/C; SizeArea_mm2: 1.28; SizeX_mm: 1.6; SizeY_mm: 0.8; EIA_Code: E96; U/M: EA; AEC Category: Q200; Green_Lifecycle: Active; Green_REACh: Passed
signal-integrity model Resistor
simulation model Resistor
footprint 0603
footprint 0603M
footprint 0603L
footprint 0603_HV
footprint 0603S
pins: 1, 2

## RC0603FR-073K48L
designator R?  ValueDisplayed: 3.48k  (hidden comment: RC0603FR-073K48L)
RES, 3.48 k, 1%, 0.1 W, 0603; Manufacturer: Yageo America; CompType: Resistor; Value: 3.48k; Res_ohm: 3480; Value_Code: 3k48; Tolerance_%: 1; Power_W: 0.1; Value2: 0.1W; VDC_V: 150; TempCo: 200 ppm/C; SizeArea_mm2: 1.28; SizeX_mm: 1.6; SizeY_mm: 0.8; EIA_Code: E96; U/M: EA; AEC Category: Q200
signal-integrity model Resistor
simulation model Resistor
footprint 0603
footprint 0603M
footprint 0603L
footprint 0603_HV
footprint 0603S
pins: 1, 2

## RC0603FR-073K57L
designator R?  ValueDisplayed: 3.57k  (hidden comment: RC0603FR-073K57L)
RES, 3.57 k, 1%, 0.1 W, 0603; Manufacturer: Yageo America; CompType: Resistor; Value: 3.57k; Res_ohm: 3570; Value_Code: 3k57; Tolerance_%: 1; Power_W: 0.1; Value2: 0.1W; VDC_V: 150; TempCo: 200 ppm/C; SizeArea_mm2: 1.28; SizeX_mm: 1.6; SizeY_mm: 0.8; EIA_Code: E96; U/M: EA; AEC Category: Q200
signal-integrity model Resistor
simulation model Resistor
footprint 0603
footprint 0603M
footprint 0603L
footprint 0603_HV
footprint 0603S
pins: 1, 2

## RC0603FR-073K65L
designator R?  ValueDisplayed: 3.65k  (hidden comment: RC0603FR-073K65L)
RES, 3.65 k, 1%, 0.1 W, 0603; Manufacturer: Yageo America; CompType: Resistor; Value: 3.65k; Res_ohm: 3650; Value_Code: 3k65; Tolerance_%: 1; Power_W: 0.1; Value2: 0.1W; VDC_V: 150; TempCo: 200 ppm/C; SizeArea_mm2: 1.28; SizeX_mm: 1.6; SizeY_mm: 0.8; EIA_Code: E96; U/M: EA; AEC Category: Q200; Green_Lifecycle: Active; Green_REACh: Passed
signal-integrity model Resistor
simulation model Resistor
footprint 0603
footprint 0603M
footprint 0603L
footprint 0603_HV
footprint 0603S
pins: 1, 2

## RC0603FR-073K74L
designator R?  ValueDisplayed: 3.74k  (hidden comment: RC0603FR-073K74L)
RES, 3.74 k, 1%, 0.1 W, 0603; Manufacturer: Yageo America; CompType: Resistor; Value: 3.74k; Res_ohm: 3740; Value_Code: 3k74; Tolerance_%: 1; Power_W: 0.1; Value2: 0.1W; VDC_V: 150; TempCo: 200 ppm/C; SizeArea_mm2: 1.28; SizeX_mm: 1.6; SizeY_mm: 0.8; EIA_Code: E96; U/M: EA; AEC Category: Q200; Green_Lifecycle: Active; Green_REACh: Passed
signal-integrity model Resistor
simulation model Resistor
footprint 0603
footprint 0603M
footprint 0603L
footprint 0603_HV
footprint 0603S
pins: 1, 2

## RC0603FR-073K83L
designator R?  ValueDisplayed: 3.83k  (hidden comment: RC0603FR-073K83L)
RES, 3.83 k, 1%, 0.1 W, 0603; Manufacturer: Yageo America; CompType: Resistor; Value: 3.83k; Res_ohm: 3830; Value_Code: 3k83; Tolerance_%: 1; Power_W: 0.1; Value2: 0.1W; VDC_V: 150; TempCo: 200 ppm/C; SizeArea_mm2: 1.28; SizeX_mm: 1.6; SizeY_mm: 0.8; EIA_Code: E96; U/M: EA; AEC Category: Q200; Green_Lifecycle: Active; Green_REACh: Passed
signal-integrity model Resistor
simulation model Resistor
footprint 0603
footprint 0603M
footprint 0603L
footprint 0603_HV
footprint 0603S
pins: 1, 2

## RC0603FR-073K92L
designator R?  ValueDisplayed: 3.92k  (hidden comment: RC0603FR-073K92L)
RES, 3.92 k, 1%, 0.1 W, 0603; Manufacturer: Yageo America; CompType: Resistor; Value: 3.92k; Res_ohm: 3920; Value_Code: 3k92; Tolerance_%: 1; Power_W: 0.1; Value2: 0.1W; VDC_V: 150; TempCo: 200 ppm/C; SizeArea_mm2: 1.28; SizeX_mm: 1.6; SizeY_mm: 0.8; EIA_Code: E96; U/M: EA; AEC Category: Q200; Green_Lifecycle: Active; Green_REACh: Passed
signal-integrity model Resistor
simulation model Resistor
footprint 0603
footprint 0603M
footprint 0603L
footprint 0603_HV
footprint 0603S
pins: 1, 2

## RC0603FR-073KL
designator R?  ValueDisplayed: 3.00k  (hidden comment: RC0603FR-073KL)
RES, 3.00 k, 1%, 0.1 W, 0603; Manufacturer: Yageo America; CompType: Resistor; Value: 3.00k; Res_ohm: 3000; Value_Code: 3k00; Tolerance_%: 1; Power_W: 0.1; Value2: 0.1W; VDC_V: 150; TempCo: 200 ppm/C; SizeArea_mm2: 1.28; SizeX_mm: 1.6; SizeY_mm: 0.8; U/M: EA; AEC Category: Q200; Green_Lifecycle: Active; Green_REACh: Passed
signal-integrity model Resistor
simulation model Resistor
footprint 0603
footprint 0603M
footprint 0603L
footprint 0603_HV
footprint 0603S
pins: 1, 2

## RC0603FR-073M01L
designator R?  ValueDisplayed: 3.01M  (hidden comment: RC0603FR-073M01L)
RES, 3.01 M, 1%, 0.1 W, 0603; Manufacturer: Yageo America; CompType: Resistor; Value: 3.01Meg; Res_ohm: 3010000; Value_Code: 3M01; Tolerance_%: 1; Power_W: 0.1; Value2: 0.1W; VDC_V: 150; TempCo: 200 ppm/C; SizeArea_mm2: 1.28; SizeX_mm: 1.6; SizeY_mm: 0.8; EIA_Code: E96; U/M: EA; AEC Category: Q200; Green_Lifecycle: Active; Green_REACh: Passed
signal-integrity model Resistor
simulation model Resistor
footprint 0603
footprint 0603M
footprint 0603L
footprint 0603_HV
footprint 0603S
pins: 1, 2

## RC0603FR-073R01L
designator R?  ValueDisplayed: 3.01  (hidden comment: RC0603FR-073R01L)
RES, 3.01, 1%, 0.1 W, 0603; Manufacturer: Yageo America; CompType: Resistor; Value: 3.01; Value_Code: 3R01; Tolerance_%: 1; Power_W: 0.1; Value2: 0.1W; VDC_V: 150; TempCo: 200 ppm/C; SizeArea_mm2: 1.28; SizeX_mm: 1.6; SizeY_mm: 0.8; EIA_Code: E96; U/M: EA; AEC Category: Q200; Green_Lifecycle: Active; Green_REACh: Passed
signal-integrity model Resistor
simulation model Resistor
footprint 0603
footprint 0603M
footprint 0603L
footprint 0603_HV
footprint 0603S
pins: 1, 2

## RC0603FR-073R32L
designator R?  ValueDisplayed: 3.32  (hidden comment: RC0603FR-073R32L)
RES, 3.32, 1%, 0.1 W, 0603; Manufacturer: Yageo America; CompType: Resistor; Value: 3.32; Value_Code: 3R32; Tolerance_%: 1; Power_W: 0.1; Value2: 0.1W; VDC_V: 150; TempCo: 200 ppm/C; SizeArea_mm2: 1.28; SizeX_mm: 1.6; SizeY_mm: 0.8; EIA_Code: E96; U/M: EA; AEC Category: Q200
signal-integrity model Resistor
simulation model Resistor
footprint 0603
footprint 0603M
footprint 0603L
footprint 0603_HV
footprint 0603S
pins: 1, 2

## RC0603FR-073R92L
designator R?  ValueDisplayed: 3.92  (hidden comment: RC0603FR-073R92L)
RES, 3.92, 1%, 0.1 W, 0603; Manufacturer: Yageo America; CompType: Resistor; Value: 3.92; Value_Code: 3R92; Tolerance_%: 1; Power_W: 0.1; Value2: 0.1W; VDC_V: 150; TempCo: 200 ppm/C; SizeArea_mm2: 1.28; SizeX_mm: 1.6; SizeY_mm: 0.8; EIA_Code: E96; U/M: EA; AEC Category: Q200
signal-integrity model Resistor
simulation model Resistor
footprint 0603
footprint 0603M
footprint 0603L
footprint 0603_HV
footprint 0603S
pins: 1, 2

## RC0603FR-074K02L
designator R?  ValueDisplayed: 4.02k  (hidden comment: RC0603FR-074K02L)
RES, 4.02 k, 1%, 0.1 W, 0603; Manufacturer: Yageo America; CompType: Resistor; Value: 4.02k; Res_ohm: 4020; Value_Code: 4k02; Tolerance_%: 1; Power_W: 0.1; Value2: 0.1W; VDC_V: 150; TempCo: 200 ppm/C; SizeArea_mm2: 1.28; SizeX_mm: 1.6; SizeY_mm: 0.8; EIA_Code: E96; U/M: EA; AEC Category: Q200; Green_Lifecycle: Active; Green_REACh: Passed
signal-integrity model Resistor
simulation model Resistor
footprint 0603
footprint 0603M
footprint 0603L
footprint 0603_HV
footprint 0603S
pins: 1, 2

## RC0603FR-074K3L
designator R?  ValueDisplayed: 4.30k  (hidden comment: RC0603FR-074K3L)
RES, 4.30 k, 1%, 0.1 W, 0603; Manufacturer: Yageo America; CompType: Resistor; Value: 4.30k; Res_ohm: 4300; Value_Code: 4k30; Tolerance_%: 1; Power_W: 0.1; Value2: 0.1W; VDC_V: 150; TempCo: 200 ppm/C; SizeArea_mm2: 1.28; SizeX_mm: 1.6; SizeY_mm: 0.8; U/M: EA; AEC Category: Q200
signal-integrity model Resistor
simulation model Resistor
footprint 0603
footprint 0603M
footprint 0603L
footprint 0603_HV
footprint 0603S
pins: 1, 2

## RC0603FR-074K7L
designator R?  ValueDisplayed: 4.70k  (hidden comment: RC0603FR-074K7L)
RES, 4.70 k, 1%, 0.1 W, 0603; Manufacturer: Yageo America; CompType: Resistor; Value: 4.70k; Res_ohm: 4700; Value_Code: 4k70; Tolerance_%: 1; Power_W: 0.1; Value2: 0.1W; VDC_V: 150; TempCo: 200 ppm/C; SizeArea_mm2: 1.28; SizeX_mm: 1.6; SizeY_mm: 0.8; U/M: EA; AEC Category: Q200; Green_Lifecycle: Active; Green_REACh: Passed
signal-integrity model Resistor
simulation model Resistor
footprint 0603
footprint 0603M
footprint 0603L
footprint 0603_HV
footprint 0603S
pins: 1, 2

## RC0603FR-074K12L
designator R?  ValueDisplayed: 4.12k  (hidden comment: RC0603FR-074K12L)
RES, 4.12 k, 1%, 0.1 W, 0603; Manufacturer: Yageo America; CompType: Resistor; Value: 4.12k; Res_ohm: 4120; Value_Code: 4k12; Tolerance_%: 1; Power_W: 0.1; Value2: 0.1W; VDC_V: 150; TempCo: 200 ppm/C; SizeArea_mm2: 1.28; SizeX_mm: 1.6; SizeY_mm: 0.8; EIA_Code: E96; U/M: EA; AEC Category: Q200; Green_Lifecycle: Active; Green_REACh: Passed
signal-integrity model Resistor
simulation model Resistor
footprint 0603
footprint 0603M
footprint 0603L
footprint 0603_HV
footprint 0603S
pins: 1, 2

## RC0603FR-074K22L
designator R?  ValueDisplayed: 4.22k  (hidden comment: RC0603FR-074K22L)
RES, 4.22 k, 1%, 0.1 W, 0603; Manufacturer: Yageo America; CompType: Resistor; Value: 4.22k; Res_ohm: 4220; Value_Code: 4k22; Tolerance_%: 1; Power_W: 0.1; Value2: 0.1W; VDC_V: 150; TempCo: 200 ppm/C; SizeArea_mm2: 1.28; SizeX_mm: 1.6; SizeY_mm: 0.8; EIA_Code: E96; U/M: EA; AEC Category: Q200; Green_Lifecycle: Active; Green_REACh: Passed
signal-integrity model Resistor
simulation model Resistor
footprint 0603
footprint 0603M
footprint 0603L
footprint 0603_HV
footprint 0603S
pins: 1, 2

## RC0603FR-074K32L
designator R?  ValueDisplayed: 4.32k  (hidden comment: RC0603FR-074K32L)
RES, 4.32 k, 1%, 0.1 W, 0603; Manufacturer: Yageo America; CompType: Resistor; Value: 4.32k; Res_ohm: 4320; Value_Code: 4k32; Tolerance_%: 1; Power_W: 0.1; Value2: 0.1W; VDC_V: 150; TempCo: 200 ppm/C; SizeArea_mm2: 1.28; SizeX_mm: 1.6; SizeY_mm: 0.8; EIA_Code: E96; U/M: EA; AEC Category: Q200
signal-integrity model Resistor
simulation model Resistor
footprint 0603
footprint 0603M
footprint 0603L
footprint 0603_HV
footprint 0603S
pins: 1, 2

## RC0603FR-074K42L
designator R?  ValueDisplayed: 4.42k  (hidden comment: RC0603FR-074K42L)
RES, 4.42 k, 1%, 0.1 W, 0603; Manufacturer: Yageo America; CompType: Resistor; Value: 4.42k; Res_ohm: 4420; Value_Code: 4k42; Tolerance_%: 1; Power_W: 0.1; Value2: 0.1W; VDC_V: 150; TempCo: 200 ppm/C; SizeArea_mm2: 1.28; SizeX_mm: 1.6; SizeY_mm: 0.8; EIA_Code: E96; U/M: EA; AEC Category: Q200; Green_Lifecycle: Active; Green_REACh: Passed
signal-integrity model Resistor
simulation model Resistor
footprint 0603
footprint 0603M
footprint 0603L
footprint 0603_HV
footprint 0603S
pins: 1, 2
